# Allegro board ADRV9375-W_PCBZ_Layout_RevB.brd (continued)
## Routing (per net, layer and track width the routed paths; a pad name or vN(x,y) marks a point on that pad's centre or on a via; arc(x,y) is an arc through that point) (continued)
VDD_IF: length 250.6
  TOP w0.203: U403.8 117.21,60.84 v1(117.49,60.57)
  TOP w0.254: U101.M12 v2(38.04,50.78)
  TOP w0.305: R513.1 97.56,57.13 v1(97.05,57.64) ; R512.1 100.09,52.69 v1(100.09,52.12) 100.09,51.22 98.32,49.45 93.34,49.45 R510.1 ; U405.1 118.84,60.76 118.64,60.57 v1(117.49,60.57) ; R511.1 v1(94.81,57.64) ; U405.8 v1(122.74,66.3) ; 51.03,16.31 51.35,15.99 U702.2 ; 51.01,17.05 51.41,16.64 U702.1 ; R606.1 55.25,26.09 v1(56.78,24.56) ; v1(123.51,32.78) 122.53,33.76 U404.1 120.98,33.76 120.51,34.24 120.51,34.57 120.01,35.06 U404.4 ; v2(137.83,52.96) 137.92,53.04 R809.1 R808.1 ; R739.2 50.3,16.65
  TOP w0.394: P504.1 v1(43.47,72.38) ; R503.1 132.75,25.02 v2(132.75,25.02)
  TOP w0.508: P707.1 48.08,15.29 ; P707.1 47,14.21 ; P707.1 47,16.37 ; P707.1 45.92,15.29
  TOP w0.762: v1(131.48,22.48) 131.45,22.45 R738.2
  L3_PWR w0.508: v1(94.81,57.64) 95.64,58.46 96.52,58.46 97.05,57.93 v1(97.05,57.64) 100.09,54.61 v1(100.09,52.12)
  L3_PWR w0.635: v1(77.1,31.42) v1(77.86,31.42) 77.87,31.41 v1(78.75,31.41) 80.03,30.12 85.37,30.12 85.83,29.67 93.51,29.67 95.23,27.96 118.91,27.96 119.45,28.49 122.21,28.49 123.51,29.8 ; v1(131.48,22.48) 132.75,23.75 v2(132.75,25.02) 131.5,26.27 127.04,26.27 123.51,29.8 ; 123.51,29.8 v1(123.51,32.78)
  L12_PWR w0.203: 56.78,22.65 v1(56.78,24.56)
  L12_PWR w0.508: 125.36,52.88 125.36,59.86 122.74,62.49 v1(122.74,66.3) ; P707.1 48.08,15.29 ; P707.1 45.92,15.29 ; P707.1 47,14.21 ; P707.1 47,16.37 ; v1(117.49,60.57) 116.28,60.57 115.2,59.48 115.2,53.13
  L12_PWR w0.762: 78.5,57.7 78.5,58.59 76.97,60.12 72.65,60.12 71.38,61.39 71.38,67.1 69.99,68.5 69.99,72.82 68.34,74.47 45.56,74.47 v1(43.47,72.38) ; v2(38.04,50.78) 41.47,50.78 43.63,52.94 45.53,52.94 48.27,55.67 76.08,55.67
  BOTTOM w0.305: v2(38.04,50.78) 38.05,50.79 C642.1 ; C642.1 R502.1 ; C642.1 38.05,52.33 C643.1
  BOTTOM w0.394: v1(122.74,66.3) 122.81,66.23 C417.2 ; C415.2 122.7,33.33 123.26,32.78 v1(123.51,32.78) 123.51,34.14 125.61,36.24 v1(125.61,36.88) ; P801.J39 v2(132.75,25.02) ; P801.K40 v1(131.48,22.48)
  BOTTOM w0.508: C734.2 49.64,16.06 C735.2
  BOTTOM w0.762: C734.2 48.87,15.29 P707.1
VDD_IF_LDO: length 2.9
  TOP w0.254: 58.1,16.32 58.1,15.16 57.63,14.69 U702.5
  TOP w0.305: U702.7 56.66,16.06
  vias: v1(57.41,17.5) v1(58.47,18.72) v1(58.43,17.45) v1(58.94,18.08) v1(59.45,18.72) v1(59.45,17.51)
VDDA_CALPLL: length 17.1
  TOP w0.254: v2(33.24,43.58) U101.G4
  L7_SIG w0.203: v2(33.24,43.58) 33.5,43.58 33.88,43.19 34.16,43.19 34.43,42.93 34.43,41.58
  L7_SIG w0.394: 34.43,41.58 34.43,36.88 33.03,35.48 32.49,35.48 31.89,34.88 v1(31.89,33.19)
  BOTTOM w0.305: v2(33.24,43.58) 33.24,43.69 33.62,44.07 C615.1
  BOTTOM w0.508: v1(31.89,33.19) 31.89,31.99 C614.1 32.11,31.77 32.11,30.34 E602.2
VDDA_CLK: length 4.7
  TOP w0.254: v2(38.84,41.18) U101.N1
  BOTTOM w0.305: C616.1 41.03,40.76 E603.2 ; v2(38.84,41.18) 38.89,41.12 C617.1 40.47,41.12 40.86,40.74
  BOTTOM w0.394: C616.1 40.86,40.74
VDDA_CLKSYNTH: length 23.2
  TOP w0.254: v2(33.24,45.18) U101.G6
  L3_PWR w0.127: v1(47.25,40.43) 47,40.69 41.54,40.69 39.99,39.14 36.97,39.14 36.42,39.68 36.06,39.68 34.42,41.33 34.42,44.53 34.2,44.76 33.66,44.76 v2(33.24,45.18)
  BOTTOM w0.305: v1(47.25,40.43) 47.17,40.35 E604.2 46.08,40.36 C618.1 ; C619.1 33.23,45.18 v2(33.24,45.18)
VDDA_DES: length 38.8
  TOP w0.254: v2(39.64,47.58) U101.P9 v2(39.64,48.38) ; U101.N9 v2(38.84,48.38)
  BOTTOM w0.305: C653.1 38.76,49.91 38.76,49.6 38.42,49.26 C654.1 38.42,48.8 v2(38.84,48.38) v2(39.64,48.38) 39.64,48.05 v2(39.64,47.58)
  BOTTOM w0.508: 39.64,48.05 39.71,48.13 48.95,48.13 52.71,44.37 55,44.37 59.73,39.64 59.73,38.32 61.55,36.5 61.73,36.5 62.6,35.63 C652.1 62.23,33.93 60.05,33.93 E613.2
VDDA_RXLO: length 17
  TOP w0.254: U101.C6 v2(30.04,45.18)
  L12_PWR w0.508: v4(25.66,43.99) 21.6,39.92 v1(20.96,39.92)
  BOTTOM w0.203: C621.1 28.46,45.18
  BOTTOM w0.305: C620.1 26.45,45.5 27.2,45.5 27.52,45.18 v2(30.04,45.18)
  BOTTOM w0.394: C620.1 26.17,45.51 25.79,45.13 25.79,44.12 v4(25.66,43.99)
  BOTTOM w0.508: E605.2 17.76,40.92 20.29,40.92 20.71,40.5 20.71,40.18 v1(20.96,39.92)
VDDA_RXSYNTH: length 25.6
  TOP w0.254: U101.G9 v2(34.04,47.58)
  L5_SIG w0.114: 34.39,45.3 33.57,46.12 33.57,47.11 v2(34.04,47.58)
  L5_SIG w0.127: 34.39,45.3 34.39,41.1
  L5_SIG w0.203: 34.39,41.1 35.77,39.72 36.44,39.72 37.02,39.14 39.99,39.14 41.83,40.98 43.4,40.98
  L5_SIG w0.305: v1(45.6,38.15) 45.6,38.63 45.81,38.83 45.81,39.75 44.57,40.98 43.4,40.98
  BOTTOM w0.305: C623.1 34.07,47.54 v2(34.04,47.58) ; E606.2 C622.1 45.87,37.37 45.6,37.64 v1(45.6,38.15)
VDDA_RXTX: length 33.8
  TOP w0.203: v2(33.24,42.78) U101.F2
  L10_SIG w0.203: 34.05,41.45 34.42,41.82 34.42,42.13 34.16,42.39 33.88,42.39 33.56,42.72 33.29,42.72 v2(33.24,42.78) 33.24,42.49 33.66,42.07 33.66,41.82 34.03,41.45 34.05,41.45
  L10_SIG w0.394: v1(42.43,26.21) v1(41.67,26.21) 40.9,26.97 40.05,26.97 37.49,29.53 37.18,29.53 35.36,31.34 35.36,34.29 34.68,34.97 34.68,40.79 34.03,41.45
  BOTTOM w0.305: v2(33.24,42.78) 33.47,42.78 33.75,43.06 C610.1 35.26,43.06 C609.1
  BOTTOM w0.394: v1(41.67,26.21) v1(42.43,26.21) 43.95,26.21 44.71,26.97 C608.1 48.27,26.97
VDDA_RXVCO: length 21.4
  TOP w0.254: U101.C7 v2(30.04,45.98)
  L12_PWR w0.394: v4(27.19,46.53) 26.42,46.53 24.9,45 24.66,45 v1(24.16,44.5)
  BOTTOM w0.305: C624.1 27.96,46.78 28.33,46.78 28.62,46.49 C625.1 29,46.49 29.52,45.98 v2(30.04,45.98)
  BOTTOM w0.394: v4(27.19,46.53) 27.58,46.92 C624.1 ; 11.44,42.97 11.57,43.1 23.12,43.1 24.01,43.99 24.01,44.35 v1(24.16,44.5)
VDDA_SER: length 31.6
  TOP w0.254: U101.N8 v2(38.84,46.78) U101.P8 v2(39.64,46.78)
  BOTTOM w0.305: C613.1 39.96,46.78 v2(39.64,46.78) v2(38.84,46.78)
  BOTTOM w0.394: C613.1 40.2,45.56 C612.1
  BOTTOM w0.508: C612.1 40.47,45.69 40.48,45.69 46.16,45.69 46.24,45.77 47.63,45.77 48.61,44.8 48.61,44.54 51.36,41.79 53.9,41.79 56.88,38.8 C611.1 56.52,33.93 54.33,33.93 E601.2
VDDA_SNRXSYNTH: length 23.7
  TOP w0.254: U101.G7 v2(34.04,46.78)
  L12_PWR w0.127: 30.48,47.99 31,47.99 31.11,48.1 33.23,48.1 33.61,47.73 33.61,47.21 v2(34.04,46.78)
  L12_PWR w0.394: v1(21.92,49.32) 22.68,50.08 25.08,50.08 25.83,49.34 26.33,49.34 27.11,48.56 29.35,48.56 29.91,47.99 30.48,47.99
  BOTTOM w0.305: v2(34.04,46.78) 34.11,46.71 C627.1
  BOTTOM w0.394: E608.2 16.45,51.61 18.14,51.61 C626.1 20.11,52.09 22.11,50.08 22.11,49.51 v1(21.92,49.32)
VDDA_SNRXVCO: length 18.6
  TOP w0.254: v2(30.04,43.58) U101.C4
  L12_PWR w0.203: 27.17,42.64 28.52,43.99 29.63,43.99 v2(30.04,43.58)
  L12_PWR w0.508: v1(26.93,38.65) 27.31,39.04 27.31,41.19 27.19,41.31 27.19,41.32 27.17,41.34 27.17,42.64
  BOTTOM w0.203: C629.1 30.17,44.18 30.04,44.05 v2(30.04,43.58)
  BOTTOM w0.508: E609.2 24.23,31.35 C628.1 26.23,34.97 26.43,35.5 v1(26.93,38.65)
VDDA_TXLO: length 29.8
  TOP w0.254: v6(33.24,50.78) U101.F12
  L10_SIG w0.394: v5(34.03,50.71) 33.97,50.78 v6(33.24,50.78)
  L12_PWR w0.203: v5(34.03,50.71) 33.89,50.57 33.05,50.57 31.66,51.96 31.47,51.96
  L12_PWR w0.394: v1(15,63.42) 15.09,63.32 17.49,63.32 18.4,62.42 18.91,62.42 22.87,58.47 24.77,58.47 29.09,54.15 29.09,53.51 30.31,52.29 31.15,52.29 31.47,51.96
  BOTTOM w0.305: C635.1 34.07,50.75 v5(34.03,50.71)
  BOTTOM w0.394: E612.2 13.34,62.78 C634.1 v1(15,63.42)
VDDA_TXSYNTH: length 29.6
  TOP w0.254: v6(33.24,47.58) U101.G8
  L10_SIG w0.127: v6(33.24,47.58) 32.85,47.97 29.81,47.97 29.6,48.18 29.6,48.56 29.44,48.72 28.78,48.72 28.74,48.76
  L10_SIG w0.254: 28.74,48.76 27.97,48.76 27.57,49.16 27.57,50.2 27.82,50.46 27.82,52.37 28.08,52.62 v1(28.08,52.98) 24.65,56.4 20.42,56.4 19.33,55.31 15.3,55.31 v1(15.2,55.21)
  BOTTOM w0.305: C633.1 28.25,53.15 v1(28.08,52.98)
  BOTTOM w0.394: v1(15.2,55.21) 13.94,55.21 C632.1 13.73,55.16 E611.2
VDDA_TXVCO: length 32
  TOP w0.254: v6(33.24,49.18) U101.F11
  L5_SIG w0.203: 27.06,49.71 27.98,48.79 30.18,48.79 30.46,48.52 30.46,48.22 30.68,47.99 33.66,47.99 v5(34.04,48.38)
  L5_SIG w0.305: v6(33.24,49.18) 34.01,49.18 v5(34.04,49.21)
  L5_SIG w0.394: v1(15,59.8) 16.11,58.69 19.72,58.69 23.22,55.2 23.22,52.91 26.42,49.71 27.06,49.71
  BOTTOM w0.305: 34.04,48.81 v5(34.04,49.21) ; 34.04,48.81 34.04,48.38 v5(34.04,48.38) ; 34.04,48.81 C631.1
  BOTTOM w0.394: 12.57,59.79 12.58,59.8 C630.1 ; 12.57,59.79 E610.2 ; 12.57,59.79 13.94,59.79 C630.1 ; v1(15,59.8) C630.1
1P3_BUCK_OUT: length 25.4
  L8_SIG w0.394: v1(85.18,33.72) 84.4,32.94 77.23,32.94 75.41,31.12 75.41,20.1 v1(76.11,19.39) v1(76.87,19.39) v1(77.64,19.39)
  BOTTOM w0.394: v1(85.18,33.72) 85.59,33.31 R705.1
3P3V_CLK: length 43.2
  TOP w0.203: U404.6 119.82,33.58 v1(119.82,32.83)
  TOP w0.305: U405.14 v1(118.84,66.3)
  TOP w0.394: C436.2 v1(90.54,79.63) ; C437.2 v1(89.04,79.63) ; C431.2 v1(95.34,72.33) ; C422.2 v1(83.24,76.33) ; C433.2 v1(95.34,75.33) ; C421.2 v1(83.24,77.83) ; C438.2 v1(87.54,79.63) ; C429.2 v1(95.34,69.33) ; C434.2 v1(93.54,79.63) ; C439.2 v1(86.04,79.63) ; v1(85.94,67.54) 85.94,67.54 86.04,67.63 C426.2 ; C435.2 v1(92.04,79.63) ; C424.2 v1(83.28,73.33) ; C425.2 83.31,69.86 v1(83.2,69.75) ; C414.2 74.91,79.05 v1(74.93,79.04) ; v1(83.22,74.83) C423.2 ; C432.2 v1(95.34,73.83) ; C428.2 v1(93.54,67.53) ; C430.2 v1(95.34,70.83) ; C427.2 v1(89.04,67.53)
  BOTTOM w0.203: U401.16 86.04,68.45 ; U401.51 92.04,78.53 ; U401.1 v1(93.54,67.53) ; 94.41,70.83 94.41,70.83 U401.69 ; 89.04,68.45 89.04,68.45 U401.10 ; U401.45 89.04,78.53 ; U401.36 84.34,77.83 ; U401.63 94.24,73.83
  BOTTOM w0.254: v1(95.34,69.33) U401.72 ; U401.33 v1(83.24,76.33) ; v1(83.2,69.75) 83.66,69.75 83.72,69.81 83.8,69.81 83.82,69.83 U401.20 ; 84.34,77.83 v1(83.24,77.83) ; 89.04,78.53 v1(89.04,79.63) ; U401.39 v1(86.04,79.63) ; U401.42 87.54,79.63 v1(87.54,79.63) ; U401.27 v1(83.28,73.33) ; U401.30 v1(83.22,74.83) ; U401.54 v1(93.54,79.63) ; 86.04,68.45 86.04,67.63 85.94,67.54 v1(85.94,67.54) ; 92.04,78.53 v1(92.04,79.63) ; U401.66 v1(95.34,72.33) ; U401.60 v1(95.34,75.33) ; 94.24,73.83 v1(95.34,73.83) ; U401.48 v1(90.54,79.63) ; 89.04,68.45 v1(89.04,67.53) ; 94.41,70.83 v1(95.34,70.83)
  BOTTOM w0.305: U402.5 v1(74.93,79.04)
  BOTTOM w0.394: C420.1 93.55,79.63 v1(93.54,79.63) ; C416.2 v1(119.82,32.83) ; R416.1 82.98,69.53 v1(83.2,69.75) ; v1(118.84,66.3) 118.87,66.26 C418.2
  vias: v1(109.99,31.73) v1(109.99,30.97) v1(110.88,31.73) v1(110.88,30.97) v1(111.77,31.73) v1(111.77,30.97)
3P3V_VCO: length 65
  BOTTOM w0.305: 127.01,74.97 127.01,74.96 C738.2
  BOTTOM w0.394: Y401.6 Y403.4 Y402.6 C405.2 v1(109.41,76.5)
  BOTTOM w0.508: R408.2 124.35,72.91 124.82,73.39 125.56,74.13 v1(125.56,74.97) v1(126.23,74.97) 127.53,74.97 130.06,72.44 130.06,54.83 126.97,51.74 126.5,51.74 120.53,45.77 118.75,45.77 116.21,43.23 114.18,43.23 111.13,40.18 109.86,40.18 107.97,38.29 103.91,38.29 E706.2
3P3VAUX: length 101.7
  TOP w0.305: U601.17 U601.16 ; U601.10 v1(45.49,22.29) ; U801.8 C803.2 125.17,31.99 125.17,31.99 C804.1 127.52,31.96 v1(127.68,31.96) ; R818.2 113.21,33.43 v1(112.97,33.67) ; R820.2 v1(113.8,30.53) ; R822.2 v1(113.8,28.75)
  TOP w0.635: U601.16 50.55,22.29 51.2,21.64 v7(51.2,20.37)
  L10_SIG w0.394: v7(51.2,20.37) 50.18,21.38 46.4,21.38 v1(45.49,22.29)
  L10_SIG w0.762: v7(51.2,20.37) 52.84,20.37 57.03,16.18 59.19,16.18 61.6,13.76 106.05,13.76 113.8,21.51 v1(113.8,28.75) v1(113.8,30.53) 113.8,32.83 v1(112.97,33.67)
  BOTTOM w0.394: C648.1 51.19,20.38 v7(51.2,20.37) 50.91,20.37 50.22,21.07 C649.1 ; P801.D32 v2(139.1,33.91)
ADP5054_EN: length 108.4
  TOP w0.305: v1(79.68,31.76) 79.66,31.77 R702.1
  L8_SIG w0.394: v2(140.3,73.57) 142.46,73.57 143.57,72.45 143.57,38.84 143.52,38.78 143.52,38.74 141.89,37.12 141.39,37.12 137.17,32.89 137.17,32.39 135.52,30.74 127.56,30.74 126.25,32.05 122.82,32.05 122.42,32.45 121.66,32.45 121.39,32.18 120.1,32.18 120.09,32.17 119.55,32.17 119.54,32.18 116.34,32.18 115.71,32.81 98.31,32.81 97.31,31.81 79.73,31.81 v1(79.68,31.76)
  BOTTOM w0.394: v2(140.3,73.57) 139.74,73.01 P801.D1
ADP5054_VREG: length 20.4
  TOP w0.394: v1(89.62,30.8) 91.4,29.02 91.4,21.83 v1(91.07,21.5) 91.04,21.53 91.04,21.68 90.64,22.08 88.95,22.08 v1(88.25,21.38) 87.86,20.99 87.86,20.73 R703.2
  BOTTOM w0.203: C702.2 89.7,30.87 v1(89.62,30.8) 89.03,30.2 ; 89.03,30.2 88.75,29.92 U701.44 ; 89.03,30.2 89.25,29.98 U701.45
  BOTTOM w0.254: v1(91.07,21.5) 90.75,21.82 U701.13 ; U701.18 v1(88.25,21.38)
AUXADC_0: length 66
  TOP w0.254: U101.E13 v6(31.64,51.58)
  L5_SIG w0.114: P501.3 81.29,66.02 79.13,68.18 72.46,68.18 70.3,66.02 70.3,61.96 68.38,60.04 47.71,60.04 47.22,60.53 46.14,60.53 45.65,60.04 44.68,60.04 44.38,60.34 44.38,60.38 44.26,60.5 39.82,60.5 37.86,58.53 36.65,58.53 34.68,56.56 34.68,53.13 32.79,51.24 31.97,51.24 v6(31.64,51.58)
  BOTTOM w0.203: C506.1 P501.3
AUXADC_1: length 90
  TOP w0.254: U101.C11 v6(30.04,49.98)
  L5_SIG w0.114: P501.4 82.46,63.58 82.46,67.33 80.43,69.35 68.17,69.35 67.84,69.02 66.29,69.02 65.82,69.5 63.15,69.5 61.86,70.79 55.82,70.79 54.9,69.87 47.84,69.87 47.8,69.9 47,69.9 45.86,68.75 40.78,68.75 37.47,72.06 35.7,72.06 35.63,72.13 31.71,72.13 31.27,71.69 30,71.69 28.77,70.47 28.77,67.55 28.08,66.85 27.44,66.85 26.99,66.4 26.99,61.56 26.53,61.09 26.51,61.09 25.66,60.24 25.66,56.01 28.77,52.9 28.77,52.18 29.04,51.91 29.38,51.91 29.6,51.69 29.6,50.41 v6(30.04,49.98)
  BOTTOM w0.203: C505.1 P501.4
AUXADC_2: length 64.2
  TOP w0.254: U101.C12 v6(30.04,50.78)
  L5_SIG w0.114: P501.5 78.75,66.02 77.29,67.48 72.84,67.48 70.88,65.52 70.88,61.99 70.88,61.99 70.88,61.56 70.88,61.56 70.88,61.04 69.19,59.36 46.93,59.36 46.68,59.61 39.76,59.61 38.01,57.86 36.94,57.86 35.19,56.11 35.19,53.13 33.97,51.91 33.9,51.91 33.7,51.72 32.39,50.4 30.41,50.4 v6(30.04,50.78)
  BOTTOM w0.203: 78.75,66.42 P501.5
AUXADC_3: length 64.8
  TOP w0.254: U101.D11 v6(30.84,49.98)
  L5_SIG w0.114: v6(30.84,49.98) 31.17,49.64 32.58,49.64 32.9,49.96 32.9,50.12 33.1,50.31 33.38,50.31 33.7,50.63 33.7,50.85 33.9,51.05 34.12,51.05 34.43,51.35 34.43,51.86 35.63,53.07 35.63,55.12 36.28,55.77 36.39,55.77 37.44,56.82 39.25,56.82 40.59,58.15 42.62,58.15 43.5,59.04 45.1,59.04 45.42,58.72 69.48,58.72 71.38,60.63 71.38,65.13 73.22,66.98 75.89,66.98 77.42,65.45 77.42,63.74 P501.6
  BOTTOM w0.203: 78.75,60.93 P501.6
BAL_TX_OUT1: length 1
  TOP w0.203: 35.44,63.14 35.44,63.48 ; 35.44,64.07 C305.1
  TOP w0.394: 35.44,63.48 35.44,64.07
BAL_TX_OUT2: length 1
  TOP w0.203: 34.24,30.41 34.23,30.07 ; C306.1 34.23,29.48
  TOP w0.394: 34.23,29.48 34.23,30.07
CLK+: length 7.5
  BOTTOM w0.203: U401.2 93.04,67.83 92.97,67.76 92.97,65.32 92.06,64.42 92.06,63.69 92.28,63.47 92.72,63.47 ; C402.2 93.54,63.47 92.72,63.47 ; R406.1 92.72,63.47
CLK-: length 8.1
  BOTTOM w0.203: U401.3 92.54,67.83 92.61,67.76 92.61,65.47 91.7,64.56 91.7,63.55 92.13,63.12 92.72,63.12 ; C403.2 93.54,63.12 92.72,63.12 ; 92.72,63.12 R406.2
CLK_RESETB: length 109.6
  TOP w0.203: v1(120.18,35.62) 119.33,35.62 119.1,35.38 119.1,34.74 119.43,34.41 U404.5
  L7_SIG w0.114: v1(120.18,35.62) 120.18,35.45 120.91,34.72 125.36,34.72 127.64,37 135.24,37 137.37,39.14 137.37,39.18 137.64,39.45 137.69,39.45 138.87,40.64 138.87,41.25 142.25,44.62 142.25,59.61 141.94,59.92 137.82,59.92 137.68,59.77 134.72,59.77 132.09,62.4 127.39,62.4 125.23,64.56 117.61,64.56 114.94,67.23 94.75,67.23 92.92,69.06 v1(83.45,69.06)
  BOTTOM w0.203: v1(83.45,69.06) 83.72,69.33 U401.19
  BOTTOM w0.394: R416.2 82.93,68.54 v1(83.45,69.06)
CLK_SYSREF_REQUEST: length 32.4
  TOP w0.203: U405.13 v1(119.49,69.23)
  L7_SIG w0.114: v1(119.49,69.23) 117.04,71.67 102.75,71.67 99.96,74.47 98.31,74.47 96.53,76.24 v1(96.53,77.8)
  BOTTOM w0.254: U401.57 94.92,76.83 95.57,76.83 v1(96.53,77.8) ; R417.2 97.17,77.8
  BOTTOM w0.394: 97.17,77.8 v1(96.53,77.8)
COMP_OUT: length 4.9
  BOTTOM w0.203: Y401.5 Y402.5 111.38,73.96 110.59,73.18 R411.1
DEV_CLK_IN+: length 66.7
  BOTTOM w0.203: 32.21,48.56 32.21,49.34 arc(32.44,50.7) 33.1,51.9 arc(35.41,53.73) 38.29,54.35 42.12,54.35 arc(44.94,55.52) 46.11,58.34 46.11,63.14 arc(47.52,66.56) 50.94,67.97 50.94,67.97 arc(58.87,68.59) 66.64,70.3 arc(73.86,71.88) 81.24,72.41 81.75,72.41 ; 32.21,48.56 R501.2 ; 32.21,48.56 32.21,48.29 arc(32.24,48.12) C502.1 ; 81.75,72.41 83.63,72.41 83.72,72.33 U401.25 ; 81.75,72.41 R425.1
DEV_CLK_IN-: length 67.3
  BOTTOM w0.203: U401.26 83.68,72.83 83.62,72.77 81.75,72.77 ; 81.75,72.77 R425.2 ; 81.75,72.77 81.24,72.77 arc(73.81,72.23) 66.54,70.64 arc(58.82,68.94) 50.94,68.32 arc(47.27,66.81) 45.75,63.14 45.75,58.34 arc(44.69,55.77) 42.12,54.7 38.29,54.7 arc(35.26,54.05) 32.83,52.13 arc(32.1,50.82) 31.85,49.34 31.85,48.56 ; 31.85,48.56 R501.1 ; 31.85,48.56 31.85,48.29 arc(31.81,48.12) C501.1
DIR_CLK+: length 4.6
  BOTTOM w0.203: 96.02,63.47 95.2,63.47 C402.1 ; 96.02,63.47 R405.1 ; 96.02,63.47 96.85,63.47 R403.2 97.49,64.12 97.99,64.12 98.43,64.56 T401.1
DIR_CLK-: length 4.6
  BOTTOM w0.203: C403.1 95.2,63.12 96.02,63.12 ; 96.02,63.12 96.83,63.12 R404.1 97.46,62.49 98.01,62.49 98.48,62.02 T401.3 ; 96.02,63.12 R405.2
EPROM_A0: length 115.9
  TOP w0.203: U601.11 47.52,20.89 v1(46.87,20.24)
  TOP w0.305: R818.1 R819.2 115.77,32.79 116.61,31.95 U801.1 118.85,31.95 v1(119.89,30.91)
  L8_SIG w0.114: v1(46.87,20.24) 48.39,21.76 52.34,21.76 57.67,16.43 80.78,16.43 81.86,17.51 94.18,17.51 102.5,25.83 114.31,25.83 119.39,30.91 v1(119.89,30.91)
  L10_SIG w0.114: v1(119.89,30.91) 124.08,26.72 136.53,26.72 137.37,27.55 137.37,27.75 139.72,30.1 v2(141.64,30.1)
  BOTTOM w0.394: P801.C34 v2(141.64,30.1)
EPROM_A1: length 115.9
  TOP w0.203: U601.13 48.52,20.62 v1(48.14,20.24)
  TOP w0.305: R820.1 R821.2 116.11,31.65 116.46,31.3 U801.2 118.64,31.3 v1(118.85,31.09)
  L8_SIG w0.114: v1(48.14,20.24) 49.03,21.13 52.21,21.13 57.61,15.73 97.23,15.73 105.8,24.3 114.31,24.3 120.53,30.53 120.53,31.03 120.02,31.54 119.26,31.54 118.85,31.13 v1(118.85,31.09)
  L10_SIG w0.114: v1(118.85,31.09) 123.98,25.95 137.5,25.95 v2(140.37,28.83)
  BOTTOM w0.394: P801.D35 v2(140.37,28.83)
FMC_CLK_RESETB: length 24
  TOP w0.305: v2(140.37,41.53) 138.57,39.73 138.57,37.52 136.91,35.86 130.82,35.86 130.37,35.41 123.77,35.41 122.77,34.41 U404.2
  BOTTOM w0.394: v2(140.37,41.53) P801.D26
FMC_SYSREF_REQUEST: length 48.9
  TOP w0.203: U405.2 v1(119.49,63.29)
  L8_SIG w0.114: v1(119.49,63.29) 121.74,61.03 125.84,61.03 126.86,62.05 129.4,62.05 132.77,58.67 140.65,58.67 142.25,57.07 142.25,48.64 141.92,48.31 141.48,48.31 140.97,47.8 140.22,47.8 139.35,46.94 139.35,40.01 v2(140.37,38.99)
  BOTTOM w0.394: v2(140.37,38.99) P801.D27
FMCA_SCL: length 107.4
  TOP w0.203: v1(50.05,20.24) 49.52,20.76 U601.15
  TOP w0.305: U801.6 122.19,30.65 v1(121.8,31.03)
  L8_SIG w0.114: v1(50.05,20.24) 51.57,18.72 53.73,18.72 57.41,15.03 108.21,15.03 114.25,21.07 114.25,23.22 120.91,29.89 120.91,30.15 v1(121.8,31.03)
  L10_SIG w0.114: v2(141.64,35.18) 141.06,34.59 133.87,34.59 130.69,31.41 122.68,31.41 122.31,31.03 v1(121.8,31.03)
  BOTTOM w0.394: v2(141.64,35.18) P801.C30
FMCA_SDA: length 110
  TOP w0.203: U601.14 v1(49.02,20.24)
  TOP w0.305: v1(121.82,30) U801.5
  L8_SIG w0.114: v1(121.82,30) 121.82,29.91 114.75,22.84 114.75,20.43 108.59,14.27 53.6,14.27 49.02,18.85 v1(49.02,20.24)
  L10_SIG w0.114: v1(121.82,30) 123.98,30 125.1,28.88 126.88,28.88 127.52,29.51 137.3,29.51 141.64,33.86 v2(141.64,33.91)
  BOTTOM w0.394: v2(141.64,33.91) P801.C31
FMCA_VADJ: length 13.2
  TOP w0.762: 131.44,19.44 129.45,19.44 TP812.1 ; 131.44,19.44 131.45,19.43 C732.1 ; 131.44,19.44 R738.1
  L12_PWR w0.508: TP812.1 128.3,21.61 ; TP812.1 129.31,20.59 ; TP812.1 127.28,20.59 ; TP812.1 128.3,19.57
  BOTTOM w0.394: P801.G39 v2(136.56,23.75) ; P801.E39 v2(139.1,23.75) ; P801.F40 v2(137.83,22.48) ; P801.H40 v2(134.02,23.75)
FMCA_VCC_3P3V: length 7.7
  L12_PWR w0.508: TP816.1 129.39,23.89 ; TP816.1 128.37,22.87 ; TP816.1 127.36,23.89 ; TP816.1 128.37,24.91
  BOTTOM w0.394: P801.C39 v2(141.64,23.75) ; P801.D38 v2(140.37,25.02) ; P801.D40 v2(140.37,22.48) ; P801.D36 v2(140.37,27.56)
FMCA_VCC_12P0V: length 5.9
  TOP w0.508: TP815.1 121.29,27.61 ; TP815.1 121.29,25.57 ; TP815.1 120.28,26.59 ; TP815.1 122.31,26.59
  BOTTOM w0.394: P801.C35 v2(141.64,28.83) ; P801.C37 v2(141.64,26.29)
FPGA_AUX_CLK+: length 49.2
  TOP w0.203: C805.1 140.22,70.09 139.16,71.14 138.97,71.14 137.82,72.28 134.97,72.28 134.18,73.07 131.58,73.07 130.43,74.23 126.7,74.23 126.5,74.02 122.88,74.02 121.93,74.98 102.3,74.98 v1(102.28,75)
  BOTTOM w0.203: v1(102.28,75) 102.05,74.76 99.07,74.76 ; 99.07,74.76 R429.1 ; 99.07,74.76 95.1,74.76 95.04,74.83 U401.61
FPGA_AUX_CLK-: length 49.2
  TOP w0.203: v1(102.28,74.18) 102.72,74.62 121.78,74.62 122.73,73.67 126.65,73.67 126.85,73.87 130.28,73.87 131.43,72.72 134.04,72.72 134.82,71.93 137.68,71.93 138.82,70.79 139.02,70.79 139.86,69.94 139.86,69.76 139.71,69.6 139.71,69.45 139.58,69.33 C806.1
  BOTTOM w0.203: R429.2 99.07,74.4 ; 99.07,74.4 95.11,74.4 95.04,74.33 U401.62 ; 99.07,74.4 99.07,74.41 99.68,74.41 102.06,74.41 v1(102.28,74.18)
FPGA_REF_CLK+: length 82
  TOP w0.203: v1(97.65,73.49) 98.35,73.49 103.51,78.66 132.22,78.66 133.8,77.07 141.23,77.07 145.93,72.37 145.93,62.59 146.14,62.39 146.14,61.27 145.25,60.39 145.25,51.27 144.55,50.56 143.47,50.56 143.27,50.36 C801.2
  BOTTOM w0.203: v1(97.65,73.49) 97.41,73.26 96.63,73.26 ; R422.1 96.63,73.26 ; 96.63,73.26 95.11,73.26 95.04,73.33 U401.64
FPGA_REF_CLK-: length 82
  TOP w0.203: C802.2 142.57,49.01 142.76,49.2 142.76,49.28 142.91,49.44 142.91,50.51 143.32,50.92 144.4,50.92 144.89,51.41 144.89,60.54 145.78,61.42 145.78,62.24 145.58,62.45 145.58,72.23 141.09,76.72 133.66,76.72 132.07,78.3 103.66,78.3 98.49,73.14 98.11,73.14 v1(97.65,72.68)
  BOTTOM w0.203: R422.2 96.63,72.9 ; 96.63,72.9 95.11,72.9 95.04,72.83 U401.65 ; 96.63,72.9 97.43,72.9 v1(97.65,72.68)
FPGA_SYSREF+: length 98.5
  L7_SIG w0.091: v2(136.56,27.56) 136.45,27.56 136.06,27.96 136.06,28.59 139.39,31.92 142,31.92 143.65,33.57 143.65,40.18 144.46,41 144.8,41 146.06,42.25 146.06,44.62 145.3,45.39 145.3,61.01 143.77,62.53 142.23,62.53 137.07,67.69 133.66,67.69 131.07,70.28 122.8,70.28 117.46,75.61 108.53,75.61 107.65,76.49 v1(98.79,76.49)
  BOTTOM w0.203: 96.72,76.26 95.16,76.26 95.09,76.33 94.47,76.33 U401.58 ; 96.72,76.26 R423.2 ; 96.72,76.26 97.33,76.26 98.56,76.26 v1(98.79,76.49)
  BOTTOM w0.394: P801.G36 v2(136.56,27.56)
FPGA_SYSREF-: length 98.5
  L7_SIG w0.091: v1(98.79,75.68) 99.35,76.24 107.54,76.24 108.43,75.36 117.36,75.36 122.69,70.02 130.97,70.02 133.55,67.44 136.96,67.44 142.12,62.28 143.67,62.28 145.04,60.9 145.04,45.28 145.81,44.52 145.81,42.36 144.7,41.25 144.36,41.25 143.39,40.28 143.39,33.68 141.89,32.18 139.28,32.18 135.8,28.7 135.8,27.76 135.6,27.56 v2(135.29,27.56)
  BOTTOM w0.203: 96.72,75.9 95.16,75.9 95.09,75.83 U401.59 ; 96.72,75.9 R423.1 ; 96.72,75.9 97.33,75.9 98.56,75.91 98.57,75.91 v1(98.79,75.68)
  BOTTOM w0.394: P801.G37 v2(135.29,27.56)
GP_INTERRUPT: length 113.4
  TOP w0.254: U101.J5 v6(35.64,45.18)
  TOP w0.394: R803.1 134.25,59.91 134.18,59.98 129.71,59.98 TP803.1
  L7_SIG w0.114: TP803.1 127.72,58.1 122.37,52.75 103.64,52.75 99.83,56.56 89.69,56.56 87.64,54.51 87.64,53.91 86.48,52.75 85.73,52.75 84.89,51.9 84.89,49.87 83.18,48.16 82.8,48.16 78.22,43.58 78.19,43.58 77.88,43.28 77.88,43.25 77.19,42.55 55.15,42.55 54.93,42.78 52.53,42.78 51.98,43.33 46.77,43.33 45.26,44.84 40.14,44.84 40.14,44.84 38.7,44.84 38.37,45.16 38.37,45.32 38.18,45.51 37.9,45.51 37.7,45.32 37.7,45.16 37.38,44.84 35.97,44.84 v6(35.64,45.18)
GPIO_0: length 110.5
  TOP w0.254: U101.K8 v6(36.44,47.58)
  TOP w0.305: R513.2 R517.1 96.26,54.23 P502.2
  L7_SIG w0.114: v2(134.02,50.42) 133.82,50.21 130.01,50.21 129.76,50.46 129.34,50.46 129.07,50.2 126.95,50.2 126.81,50.34 100.15,50.34 P502.2
  L8_SIG w0.114: v6(36.44,47.58) 36.69,47.58 37.08,47.19 39.77,47.19 40.31,46.66 43.15,46.66 43.41,46.92 44.65,46.92 44.74,46.83 45.16,46.83 45.63,47.29 46.91,47.29 47.78,48.16 50.03,48.16 51.19,49.32 66.3,49.32 72.4,55.42 79.61,55.42 79.62,55.41 80.04,55.41 80.05,55.42 81.03,55.42 82.05,56.43 94.88,56.43 96.4,54.91 P502.2
  BOTTOM w0.394: v2(134.02,50.42) P801.H19
GPIO_1: length 125.5
  TOP w0.254: U101.J8 v6(35.64,47.58)
  TOP w0.305: 98.62,52.88 98.62,52.37 R516.1 ; 98.62,52.88 R512.2 ; 98.62,52.88 95.2,52.88 P502.3
  L7_SIG w0.114: P502.3 96.09,49.31 117.63,49.31 117.64,49.32 130.91,49.32 131.55,48.69 132.56,48.69 132.56,48.69 132.95,48.69 132.95,48.69 133.56,48.69 v2(134.02,49.15)
  L8_SIG w0.114: P502.3 93.86,50.34 91.77,48.24 91.77,44.69 90.56,43.48 90.56,42.97 85.86,38.27 59.32,38.27 58.56,37.51 54.49,37.51 54.11,37.13 45.22,37.13 43.45,38.9 42.05,38.9 40.14,40.81 37.6,40.81 36.78,41.64 36.3,41.64 36.1,41.84 36.1,42.06 34.43,43.74 34.43,46.84 34.75,47.16 35.23,47.16 v6(35.64,47.58)
  BOTTOM w0.394: v2(134.02,49.15) P801.H20
GPIO_2: length 123.6
  TOP w0.254: U101.J7 v6(34.84,45.98)
  TOP w0.305: R511.2 R515.1 93.52,54.43 P502.4
  L7_SIG w0.114: P502.4 94.97,55.2 98.28,55.2 102.54,50.94 123.76,50.94 124.05,51.23 129.81,51.23 130.21,51.64 130.66,51.64 131.2,51.1 135.88,51.1 v2(136.56,50.42)
  L8_SIG w0.114: v6(34.84,45.98) 34.68,45.82 34.68,43.99 36.33,42.34 36.71,42.34 37.41,41.64 39.95,41.64 41.41,40.18 46.49,40.18 47.77,38.9 53.6,38.9 54.54,39.84 84.89,39.84 88.04,43 88.04,43.5 90.99,46.46 90.99,49 92.47,50.47 92.47,52.69 P502.4
  BOTTOM w0.394: v2(136.56,50.42) P801.G18
GPIO_3: length 119.7
  TOP w0.254: U101.K7 v6(36.44,46.78)
  TOP w0.305: R510.2 91.51,49.32 R514.1
  TOP w0.394: P502.5 91.46,51.41 R514.1
  L7_SIG w0.114: P502.5 93.67,49.2 93.69,49.2 94,48.9 94,48.87 95.33,47.53 115.72,47.53 116.16,47.09 118.68,47.09 119.01,47.42 133.83,47.42 133.83,47.42 134.22,47.42 134.22,47.42 134.83,47.42 v2(136.56,49.15)
  L8_SIG w0.114: v6(36.44,46.78) 36.44,45.75 35.97,45.28 35.97,45.04 35.78,44.84 35.63,44.84 35.3,44.52 35.3,44.24 35.63,43.91 35.78,43.91 36.08,43.61 36.08,43.46 36.43,43.11 36.58,43.11 36.9,42.79 36.9,42.64 37.2,42.34 40.01,42.34 41.28,41.07 48.26,41.07 48.77,40.57 52.21,40.57 52.33,40.69 62.33,40.69 62.33,40.68 83.07,40.68 83.37,40.99 83.37,41.25 89.23,47.1 89.23,49.13 91.32,51.23 P502.5
  BOTTOM w0.394: v2(136.56,49.15) P801.G19
GPIO_3P3_0: length 59.1
  TOP w0.254: v6(29.35,40.63) 29.49,40.63 U101.C1
  L8_SIG w0.114: v6(29.35,40.63) 29.24,40.63 28.85,41.02 28.85,41.53 28.46,41.93 28.46,43.74 28.81,44.08 28.81,47.62 29.23,48.04 29.38,48.04 29.39,48.05 29.4,48.05 29.7,48.36 29.7,48.52 29.9,48.71 30.09,48.71 31.3,49.92 31.3,50.12 31.5,50.31 31.66,50.31 33.54,52.19 33.54,54.46 38.81,59.74 39.13,59.74 40.65,61.26 40.65,62.66 46.49,68.5 48.52,68.5 48.78,68.25 49.67,68.25 50.05,68.63 61.48,68.63 64.02,66.09 P503.5
  BOTTOM w0.203: P503.5 64.02,66.37
GPIO_3P3_1: length 52.3
  TOP w0.254: U101.C2 v6(30.04,41.98)
  L8_SIG w0.114: v6(30.04,41.98) 29.65,42.36 29.65,47.72 29.97,48.04 30.18,48.04 30.5,48.36 30.5,48.52 30.7,48.71 30.89,48.71 31.3,49.12 31.3,49.32 31.5,49.51 31.69,49.51 32.04,49.86 32.04,50.11 34.05,52.12 34.05,53.64 36.3,55.89 36.55,55.89 37.47,56.82 39.51,56.82 40.65,57.96 40.65,59.23 43.06,61.64 43.06,63.67 44.97,65.58 45.86,65.58 47.51,67.23 50.3,67.23 50.81,67.74 56.14,67.74 57.41,66.47 59.95,66.47 P503.7
  BOTTOM w0.203: P503.7 61.48,66.37
GPIO_3P3_2: length 43
  TOP w0.254: U101.F1 v6(32.44,41.18)
  L8_SIG w0.114: P503.9 57.67,63.67 57.67,62.1 49.84,54.28 45.35,54.28 43.44,52.37 40.47,52.37 40.12,52.72 37.44,52.72 36.84,52.12 36.84,50.6 36.56,50.31 36.3,50.31 36.1,50.12 36.1,49.85 35.76,49.51 35.5,49.51 35.3,49.32 35.3,49.05 35.04,48.79 34.78,48.79 34.37,48.39 34.37,48.24 34.18,48.04 33.95,48.04 33.57,47.66 33.57,47.44 33.38,47.24 33.23,47.24 32.9,46.92 32.9,46.91 32.85,46.86 32.85,44.31 32.45,43.91 32.3,43.91 32.1,43.72 32.1,41.51 v6(32.44,41.18)
GPIO_3P3_3: length 44.8
  TOP w0.254: U101.D1 31.2,41.54 v6(31.2,41.01)
  L8_SIG w0.114: P503.11 55.13,66.21 50.3,66.21 45.98,61.9 45.98,60.75 40.24,55.01 36.98,55.01 36.7,54.74 36.41,54.74 34.5,52.83 34.5,51.56 33.99,51.05 33.9,51.05 33.7,50.85 33.7,50.76 33.25,50.31 33.1,50.31 32.9,50.12 32.9,49.96 31.66,48.71 31.5,48.71 31.3,48.52 31.3,48.36 30.98,48.04 30.83,48.04 30.43,47.64 30.43,41.79 v6(31.2,41.01)
  BOTTOM w0.203: P503.11 C525.1
GPIO_3P3_4: length 40.6
  TOP w0.254: U101.E1 v6(31.64,41.18)
  L8_SIG w0.114: v6(31.64,41.18) 31.25,41.56 31.25,43.66 31.5,43.91 31.72,43.91 32.05,44.24 32.05,46.95 33.14,48.04 33.38,48.04 33.57,48.24 33.57,48.6 33.82,48.84 34.15,48.84 34.37,49.07 34.37,49.27 34.71,49.6 34.96,49.6 35.3,49.94 35.3,50.12 35.5,50.31 35.67,50.31 35.97,50.62 35.97,52.65 37.35,54.02 42.94,54.02 44.46,55.55 46.75,55.55 52.59,61.39 52.59,63.67 P503.13
  BOTTOM w0.203: P503.13 C526.1
GPIO_3P3_5: length 35
  TOP w0.254: U101.D5 v6(30.84,44.38)
  L8_SIG w0.114: v6(30.84,44.38) 31.23,44.77 31.23,47.02 32.25,48.04 32.58,48.04 32.77,48.24 32.77,48.56 33.05,48.84 33.38,48.84 33.57,49.04 33.57,49.36 34.65,50.44 34.98,50.44 35.3,50.76 35.3,52.85 36.98,54.53 41.95,54.53 43.75,56.33 43.75,56.8 44.06,57.1 44.82,57.1 48.65,60.93 48.65,62.28 P503.15
  BOTTOM w0.203: P503.15 C527.1
GPIO_3P3_6: length 57.2
  TOP w0.254: U101.E14 v6(31.64,52.38)
  L5_SIG w0.114: v6(31.64,52.38) 31.96,52.38 32.3,52.71 32.43,52.71 32.58,52.86 32.58,54.62 31.7,55.5 31.7,56.24 32.23,56.78 32.3,56.78 32.97,57.46 32.97,59.17 34.2,60.4 34.2,62.89 36.21,64.89 36.62,64.89 37.69,65.96 45.67,65.96 45.68,65.96 46.1,65.96 46.11,65.96 46.49,65.96 46.68,66.15 48.09,66.15 48.16,66.08 49.36,66.08 49.36,66.09 56.84,66.09 57.54,65.39 57.54,61.9 58.18,61.26 61.99,61.26 62.41,61.68 62.41,61.73 62.75,62.07 62.75,62.91 63.38,63.55 67.95,63.55 P503.2
  BOTTOM w0.203: P503.2 C528.1
GPIO_3P3_7: length 57.9
  TOP w0.254: U101.D12 v6(30.84,50.78)
  L8_SIG w0.114: v6(30.84,50.78) 31.29,51.23 31.77,51.23 31.97,51.44 31.97,51.59 32.42,52.04 32.58,52.04 32.85,52.31 32.85,54.94 32.75,55.04 32.75,55.47 33.05,55.77 33.06,55.77 33.39,56.1 33.4,56.1 33.7,56.4 33.7,56.41 34.33,57.03 34.33,61.09 38.19,64.94 39.89,64.94 44.71,69.77 53.98,69.77 55.13,70.91 61.99,70.91 66.43,66.47 66.68,66.47 67.83,65.32 67.83,63.67 P503.4
  BOTTOM w0.203: P503.4 66.56,60.65
GPIO_3P3_8: length 43.6
  TOP w0.254: U101.D13 v6(30.84,51.58)
  L5_SIG w0.114: v6(30.84,51.58) 31.21,51.95 33.02,51.95 34.3,53.23 34.3,57.9 36.7,60.3 37.21,60.3 38.05,61.13 48.52,61.13 49.03,60.63 63,60.63 64.02,61.64 P503.6
  BOTTOM w0.203: P503.6 64.02,60.65
GPIO_3P3_9: length 63.3
  TOP w0.254: U101.C13 v6(30.04,51.58)
  L5_SIG w0.114: v6(30.04,51.58) 30.04,52.12 28.97,53.19 28.97,57.55 27.81,58.71 27.81,60.6 27.49,60.93 27.49,66.1 27.82,66.43 28.42,66.43 29.25,67.26 29.25,70.18 30.11,71.04 35.19,71.04 38.17,68.06 40.2,68.06 40.82,67.44 47.97,67.44 48.78,68.25 59.83,68.25 62.62,65.45 62.62,64.18 61.48,63.04 P503.8
  BOTTOM w0.203: P503.8 61.48,60.65
GPIO_3P3_10: length 54.8
  TOP w0.254: U101.D14 v6(30.84,52.38)
  L5_SIG w0.114: v6(30.84,52.38) 30.42,52.38 29.34,53.46 29.34,58.76 29.68,59.1 29.68,59.81 28.2,61.29 28.2,65.29 30.28,67.37 31.65,67.37 31.82,67.2 34.78,67.2 35.32,66.65 36.67,66.65 37.22,67.2 39.28,67.2 39.7,66.79 45.48,66.79 45.68,66.98 48.8,66.98 48.93,67.11 50.29,67.11 50.89,66.51 59.15,66.51 60.21,65.45 60.21,63.67 P503.10
  BOTTOM w0.203: P503.10 C532.1
GPIO_3P3_11: length 34
  TOP w0.254: U101.F14 v6(32.44,52.38)
  L5_SIG w0.114: P503.12 55.13,63.67 47.57,63.67 47.28,63.38 40.23,63.38 39.71,62.86 37.46,62.86 37.16,63.16 36.43,63.16 35.48,62.21 35.48,60.26 33.8,58.58 33.8,53.68 32.85,52.73 32.85,52.63 32.59,52.38 v6(32.44,52.38)
GPIO_4: length 119.4
  TOP w0.254: U101.K6 v6(36.44,45.18)
  TOP w0.305: R524.1 91.29,54.11 P502.6
  L7_SIG w0.114: P502.6 90.18,52.94 90.18,50.47 94.88,45.77 113.42,45.77 113.72,46.07 117.69,46.07 118.31,45.45 130.47,45.45 133.12,42.8 v2(134.02,42.8)
  L8_SIG w0.114: P502.6 90.12,52.88 90.12,50.66 88.45,49 88.45,48.46 88.15,48.16 87.62,48.16 83.72,44.26 62.93,44.26 61.22,42.55 55.55,42.55 55.44,42.66 54.18,42.66 53.48,41.96 49.67,41.96 49.36,41.65 41.47,41.65 39.87,43.24 38.98,43.24 37.1,43.24 36.9,43.44 36.9,43.59 36.58,43.91 36.41,43.91 36.1,44.22 36.1,44.52 36.44,44.86 v6(36.44,45.18)
  BOTTOM w0.394: v2(134.02,42.8) P801.H25
GPIO_5: length 112.3
  TOP w0.254: U101.K5 v6(36.44,44.38)
  TOP w0.305: R522.1 89.04,51.29 P502.7
  L7_SIG w0.114: v2(134.02,41.53) 133.53,41.53 131.19,43.86 122.69,43.86 122.41,44.14 118.93,44.14 118.26,43.46 117.83,43.46 117.69,43.61 107.67,43.61 107.66,43.61 107.24,43.61 107.23,43.61 93.48,43.61 90.56,46.53 90.56,47.16 88.78,48.94 P502.7
  L8_SIG w0.097: 39.51,43.99 39.89,43.99
  L8_SIG w0.114: P502.7 88.78,51.23 85.35,47.8 84.46,47.8 82.25,45.58 61.42,45.58 59.88,44.05 54.3,44.05 53.6,43.35 49.92,43.35 49.67,43.1 40.78,43.1 39.89,43.99 ; 39.51,43.99 37.15,43.99 36.76,44.38 v6(36.44,44.38)
  BOTTOM w0.394: v2(134.02,41.53) P801.H26
GPIO_6: length 120.8
  TOP w0.254: U101.L5 v6(37.24,44.38)
  TOP w0.305: P502.8 88.82,54.12 R523.1
  L7_SIG w0.114: P502.8 90.62,55.93 98.94,55.93 102.88,51.99 128.92,51.99 129.29,52.36 136.55,52.36 137.03,51.88 137.03,51.84 141.11,47.76 141.11,45.87 v2(141.64,45.34)
  L8_SIG w0.114: P502.8 87.64,52.94 87.64,50.97 86.21,49.55 86.21,49.31 86.1,49.2 82.81,49.2 82.81,49.19 82.65,49.19 80.16,46.71 80.16,46.59 79.66,46.09 60.4,46.09 59.77,45.45 57.85,45.45 56.96,44.56 55.32,44.56 55.19,44.68 49.85,44.68 49.28,44.12 40.52,44.12 39.89,44.75 37.61,44.75 v6(37.24,44.38)
  BOTTOM w0.394: v2(141.64,45.34) P801.C22
GPIO_7: length 119.8
  TOP w0.254: U101.L6 v6(37.24,45.18)
  TOP w0.305: R519.1 86.65,51.14 P502.9
  L7_SIG w0.114: v2(140.37,45.34) 140.37,44.46 137.99,42.08 135.65,42.08 134.49,40.93 132.07,40.93 131.31,41.69 130.7,41.69 130.64,41.63 127.85,41.63 127.14,42.34 121.95,42.34 121.57,41.96 120.06,41.96 119.61,42.41 113.74,42.41 113.42,42.08 93.1,42.08 91.07,44.12 90.43,44.12 89.54,45 89.54,45.64 86.24,48.94 P502.9
  L8_SIG w0.114: P502.9 85.04,50.34 80.53,50.34 80.15,49.96 80.15,49.87 79.85,49.57 79.76,49.57 77.61,47.42 60.72,47.42 59.38,46.08 49.6,46.08 48.24,44.72 47.21,44.72 47.18,44.75 40.65,44.75 39.76,45.64 38.7,45.64 37.7,45.64 v6(37.24,45.18)
  BOTTOM w0.394: P801.C23 v2(140.37,45.34)
GPIO_8: length 146.8
  TOP w0.254: U101.L12 v6(37.24,50.78)
  TOP w0.305: P502.10 86.23,54.1 86.23,56.32 R520.1
  L5_SIG w0.091: v2(136.56,42.8) 137.23,42.8 137.35,42.93 137.35,43.49 137.23,43.62 136.07,43.62 135.94,43.74 135.94,44.42 135.82,44.55 134.62,44.55 134.5,44.42 134.5,43.61 134.37,43.48 133.63,43.48 133.5,43.61 133.5,44.42 133.37,44.55 132.24,44.55 132.12,44.42 132.12,42.14 132.24,42.01 134.65,42.01 134.77,42.14 134.77,43.01 135.03,43.27 135.64,43.27 135.77,43.14 135.77,42.45 135.96,42.26 138.5,42.26 138.81,42.57 138.81,50.25 136.81,52.24 131.22,52.24 129.95,53.51 124.11,53.51 123.86,53.77 103.13,53.77 102.88,54.02 99.2,54.02 97.29,55.93 85.97,55.93 85.93,55.89 85.93,55.64 86.24,55.32 P502.10
  L10_SIG w0.091: P502.10 85.04,52.88 85.04,51.06 83.34,49.37 79.99,49.37 79.95,49.33 79.32,49.33 79.28,49.37 73.44,49.37 70.11,52.7 46.16,52.7 44.46,54.4 37.96,54.4 37.05,53.49 37.05,52.34 37.63,51.75 37.63,51.17 v6(37.24,50.78)
  BOTTOM w0.203: v2(136.56,42.8) P801.G25
GPIO_9: length 117.5
  TOP w0.254: U101.K12 v6(36.44,50.78)
  L5_SIG w0.091: v2(134.02,46.61) 134.02,46.12 134.24,45.9 134.4,45.9 134.5,46 134.5,46.8 134.18,47.13 127.92,47.13 124.52,50.53 115.62,50.53 115.05,49.96 85.72,49.96 84.82,50.86 84.82,52.18 84.27,52.73 84.05,52.73 83.7,52.37 P502.11
  L10_SIG w0.091: P502.11 83.83,51.55 83.95,51.67 83.95,52.56 83.83,52.69 72.87,52.69 68.37,57.2 41.43,57.2 40.57,58.06 37.05,58.06 35.66,56.68 35.66,52.1 35.76,52.01 35.85,52.01 36.08,51.78 36.08,51.13 v6(36.44,50.78)
  BOTTOM w0.203: v2(134.02,46.61) P801.H22
GPIO_10: length 117.5
  TOP w0.254: U101.J12 v6(35.64,50.78)
  L5_SIG w0.091: P502.12 83.7,53.4 84.12,52.98 84.38,52.98 85.07,52.29 85.07,50.97 85.83,50.21 114.94,50.21 115.52,50.79 124.63,50.79 128.03,47.38 134.28,47.38 134.76,46.91 134.76,45.89 134.51,45.65 134.33,45.65 v2(134.02,45.34)
  L10_SIG w0.091: v6(35.64,50.78) 35.31,51.1 35.31,51.77 35.41,51.87 35.41,56.78 36.94,58.31 40.67,58.31 41.54,57.45 68.47,57.45 72.98,52.94 83.61,52.94 83.7,53.03 P502.12
  BOTTOM w0.203: v2(134.02,45.34) P801.H23
GPIO_11: length 117.9
  TOP w0.254: U101.H12 v6(34.84,50.78)
  L5_SIG w0.091: P502.13 81.16,52.46 81.39,52.69 81.84,52.69 82.59,53.45 82.59,54.61 83.21,55.22 84.39,55.22 84.88,54.74 84.88,53.4 85.6,52.68 102.69,52.68 103.29,52.08 128.19,52.08 130.6,49.67 134.3,49.67 135.62,48.35 135.62,46.94 v2(135.29,46.61)
  L7_SIG w0.091: v6(34.84,50.78) 34.85,50.78 34.86,50.79 35.12,50.79 35.52,50.39 39.71,50.39 39.92,50.59 39.92,50.76 40.06,50.9 44.38,50.9 45.86,52.37 70.11,52.37 73.48,55.74 78.66,55.74 79.75,54.64 79.75,53.07 80.14,52.69 81.88,52.69 82.01,52.56 82.01,51.67 81.88,51.55 P502.13
  BOTTOM w0.203: P801.G21 v2(135.29,46.61)
GPIO_12: length 117.8
  TOP w0.254: U101.H11 v6(34.84,49.98)
  L5_SIG w0.091: v2(136.56,46.61) 135.88,47.29 135.88,48.46 134.41,49.92 130.7,49.92 128.29,52.34 103.4,52.34 102.8,52.94 85.71,52.94 85.13,53.51 85.13,54.84 84.5,55.48 83.1,55.48 82.34,54.72 82.34,53.55 81.73,52.94 81.38,52.94 81.16,53.16 P502.14
  L7_SIG w0.091: v6(34.84,49.98) 34.84,50.31 34.51,50.63 34.51,50.91 34.75,51.15 44.28,51.15 45.75,52.62 70.01,52.62 73.37,55.99 78.77,55.99 80.01,54.75 80.01,53.18 80.24,52.94 81.07,52.94 81.16,53.03 P502.14
  BOTTOM w0.203: P801.G22 v2(136.56,46.61)
GPIO_13: length 121.9
  TOP w0.254: U101.J11 v6(35.64,49.98)
  L7_SIG w0.091: P502.15 78.62,52.6 78.53,52.69 77.85,52.69 77.54,52.38 77.54,51.03 76.12,49.62 75.42,49.62 73.48,47.67 52.21,47.67 51.6,48.28 49.44,48.28 49.09,47.93 42.55,47.93 42.02,47.4 39.99,47.4 39.79,47.2 39.48,47.2 39.26,47.42 38.77,47.42 38.14,48.05 37.9,48.05 37.71,48.24 37.71,48.48 37.34,48.85 37.1,48.85 36.91,49.04 36.91,49.31 36.83,49.39 36.7,49.39 36.54,49.54 36.07,49.54 v6(35.64,49.98)
  L8_SIG w0.091: P502.15 78.62,52.03 79.29,52.7 84.42,52.7 85.13,53.41 85.13,54.74 85.82,55.42 94.14,55.42 94.96,54.59 94.96,53.56 95.87,52.65 97.78,52.65 102.75,47.67 113.21,47.67 125.52,35.36 128.36,35.36 130.23,33.49 135.45,33.49 136.15,34.2 136.15,34.77 v2(136.56,35.18)
  BOTTOM w0.203: v2(136.56,35.18) P801.G31
GPIO_14: length 121.8
  TOP w0.254: U101.K11 v6(36.44,49.98)
  L7_SIG w0.091: P502.16 78.97,54.09 79.1,53.96 79.1,53.07 78.97,52.94 77.74,52.94 77.29,52.49 77.29,51.14 76.02,49.87 75.32,49.87 73.37,47.93 52.31,47.93 51.7,48.54 49.34,48.54 48.98,48.18 42.45,48.18 41.92,47.65 40.1,47.65 39.79,47.95 39.48,47.95 39.2,47.67 38.88,47.67 38.36,48.19 38.36,48.51 38.17,48.7 37.85,48.7 37.56,48.99 37.56,49.31 37.37,49.5 37.08,49.5 36.94,49.64 36.8,49.64 36.47,49.98 v6(36.44,49.98)
  L8_SIG w0.091: v2(135.29,35.18) 135.59,35.18 135.9,34.87 135.9,34.3 135.34,33.74 130.34,33.74 128.46,35.62 125.62,35.62 113.31,47.93 102.86,47.93 97.88,52.9 95.98,52.9 95.22,53.66 95.22,54.7 94.24,55.67 85.71,55.67 84.88,54.84 84.88,53.52 84.32,52.95 79.29,52.95 78.62,53.62 P502.16
  BOTTOM w0.203: v2(135.29,35.18) P801.G30
GPIO_15: length 147
  TOP w0.254: U101.L11 v6(37.24,49.98)
  L5_SIG w0.091: P502.17 76.84,51.55 78.17,52.88 79.1,52.88 79.86,53.64 79.86,54.84 81.01,55.99 85.67,55.99 85.86,56.18 97.4,56.18 99.3,54.28 102.98,54.28 103.24,54.02 123.96,54.02 124.22,53.77 130.06,53.77 131.33,52.5 136.91,52.5 139.06,50.35 139.06,42.46 138.6,42 135.86,42 135.29,42.57 v2(135.29,42.8)
  L10_SIG w0.091: v6(37.24,49.98) 36.88,49.98 36.79,50.07 36.79,53.59 37.86,54.66 44.56,54.66 46.27,52.96 70.21,52.96 73.55,49.62 79.39,49.62 79.43,49.58 79.85,49.58 79.89,49.62 83.2,49.62 83.33,49.75 83.33,50.26 83.2,50.39 80.46,50.39 80.08,50.77 79.52,50.77 79.06,50.31 78.17,50.31 77.74,50.74 77.13,50.74 76.65,50.26 75.08,50.26 74.88,50.47 74.88,51.35 75.07,51.55 P502.17
  BOTTOM w0.203: P801.G24 v2(135.29,42.8)
GPIO_16: length 112.5
  TOP w0.254: U101.M11 v6(38.04,49.98)
  L5_SIG w0.091: v2(136.56,54.23) 136.15,54.23 136.06,54.32 136.06,55.77 135.51,56.32 132.72,56.32 132.34,56.69 122.54,56.69 122.03,57.2 116.49,57.2 114.58,55.29 104.76,55.29 103.04,57.02 80.9,57.02 80.35,57.56 79.37,57.56 77.27,55.46 77.27,53.81 76.36,52.9 75.52,52.9 75.03,52.41 74.9,52.41 74.72,52.59 74.72,52.72 P502.18
  L7_SIG w0.091: v6(38.04,49.98) 38.35,49.98 38.82,49.5 40.83,49.5 41.03,49.7 47.78,49.7 48.8,50.72 70.29,50.72 72.56,52.99 74.98,52.99 P502.18
  BOTTOM w0.394: P801.G16 v2(136.56,54.23)
GPIO_17: length 112.5
  TOP w0.254: U101.M10 v6(38.04,49.18)
  L5_SIG w0.091: P502.19 74.53,51.55 75.63,52.65 76.46,52.65 77.52,53.71 77.52,55.36 79.48,57.31 80.25,57.31 80.79,56.76 102.93,56.76 104.66,55.04 114.69,55.04 116.59,56.94 121.93,56.94 122.44,56.43 132.24,56.43 132.61,56.06 135.4,56.06 135.8,55.67 135.8,54.74 v2(135.29,54.23)
  L7_SIG w0.091: v6(38.04,49.18) 38.38,49.18 38.77,48.79 38.91,48.79 39.16,49.04 39.22,49.04 39.47,48.79 39.75,48.79 39.94,48.98 39.94,49.16 40.02,49.25 40.93,49.25 41.14,49.45 47.89,49.45 48.9,50.47 70.4,50.47 72.66,52.73 74.83,52.73 74.99,52.57 74.99,51.64 74.89,51.55 P502.19
  BOTTOM w0.394: P801.G15 v2(135.29,54.23)
GPIO_18: length 125.2
  TOP w0.254: U101.J3 v6(35.64,43.58)
  TOP w0.305: P502.20 73.66,54.2 73.66,56.13 R521.1 R518.1
  L5_SIG w0.114: v2(140.37,58.04) 137.15,61.26 130.44,61.26 129.36,62.34 127.12,62.34 124.97,64.49 105.22,64.49 100.59,59.86 87.17,59.86 87.16,59.87 79.26,59.87 73.54,54.15 P502.20
  L8_SIG w0.097: 39.41,46.38 39.76,46.38
  L8_SIG w0.114: v6(35.64,43.58) 35.47,43.58 35.01,44.04 35.01,45.68 35.19,45.85 35.19,46.02 36.28,47.11 36.58,47.11 36.85,46.84 36.85,46.62 37.08,46.38 39.41,46.38 ; 39.76,46.38 39.78,46.38 40.52,45.64 47.36,45.64 48.95,47.22 50.3,47.22 50.39,47.13 51.38,47.13 51.39,47.14 54.1,47.14 54.29,47.32 59.6,47.32 60.33,48.05 67.72,48.05 73.54,53.87 P502.20
  BOTTOM w0.203: P801.D12 139.74,58.63 139.88,58.49 139.92,58.49 v2(140.37,58.04)
INPUT_VOLTAGE: length 42.1
  TOP w0.203: 121.36,15.76 DS701.A 121.36,18.14 CR701.C
  TOP w0.305: R602.2 v1(55.9,19.99)
  L7_SIG w0.114: v1(55.9,19.99) 56.41,19.48 60.21,19.48 62.37,17.32 80.18,17.32 v1(84.09,21.22)
  BOTTOM w0.254: v1(92.49,25.87) 92.24,26.12 U701.6 ; v1(92.49,25.87) 92.24,25.62 U701.7 ; v1(92.49,25.87) 92.8,25.87 v1(93.15,25.51) ; U701.36 84.03,28.62 83.53,29.12 ; v1(85.59,21.2) 86.25,21.86 U701.22 ; 85.26,30.29 85.75,29.8 U701.38
  BOTTOM w0.394: R709.1 v1(92.94,31.09)
  vias: v1(83.38,30.98) v1(83.71,29.43) v1(84.24,30.98) v1(84.57,29.43) v1(84.82,21.2) v1(98.77,26.02) v1(98.77,25.13) v1(98.77,24.27) v7(117.74,18.72) v7(117.74,17) v7(119.26,18.72) v7(119.26,17) v7(123.71,18.72) v7(123.71,17) v7(125.23,18.72) v7(125.23,17)
JTAG_TDI: length 1.6
  TOP w0.305: R815.2 140.04,34.85 v2(140.37,35.18)
  BOTTOM w0.394: v2(140.37,35.18) P801.D30
JTAG_TDO: length 1.6
  TOP w0.305: v2(140.37,33.91) 140.07,34.21 R815.1
  BOTTOM w0.394: v2(140.37,33.91) P801.D31
LDO_VCO_2P5: length 3.4
  BOTTOM w0.254: U401.15 86.54,68.07 86.54,67.75 86.55,67.74 86.55,67.23 86.26,66.94 C412.1 86.26,66.01 86.31,65.96 C413.1
LF_EXT_CAP: length 3.1
  BOTTOM w0.203: 90.4,66.59 C410.2
  BOTTOM w0.254: U401.7 90.54,67.88 90.54,66.69 C410.2 ; R415.2 89.95,66.58 89.96,66.59 90.4,66.59
LF_PLL2: length 2.2
  BOTTOM w0.254: U401.14 87.04,67.52 87.25,67.31 C412.2
ORX1+: length 8.1
  BOTTOM w0.127: 23.36,53.8 23.4,53.61 C232.2
  BOTTOM w0.203: v5(28.84,50.38) arc(28.64,50.41) 28.43,50.42 arc(25.7,51.21) 23.68,53.21 arc(23.61,53.31) 23.55,53.42 arc(23.45,53.61) 23.36,53.8 arc(23.12,54.11) 22.82,54.35 arc(22.73,54.4) L231.1
ORX1-: length 8.5
  BOTTOM w0.127: C232.1 23.75,53.82 23.66,53.98 ; C232.1 23.77,53.84 ; C232.1 23.85,53.87
  BOTTOM w0.203: 23.75,53.82 23.85,53.87 ; 23.75,53.82 23.86,53.59 arc(23.92,53.49) 23.98,53.4 arc(25.88,51.52) 28.44,50.78 arc(28.53,50.78) 28.61,50.8 arc(28.71,50.85) 28.8,50.91 arc(28.86,51.04) v5(28.84,51.18) ; 23.75,53.82 arc(23.71,53.9) 23.66,53.98 ; 23.66,53.98 23.74,53.85 23.77,53.84 ; 23.66,53.98 arc(23.54,54.24) 23.47,54.52 arc(23.45,54.71) L230.1
ORX2+: length 7.7
  BOTTOM w0.203: C240.2 24.1,39.26 ; 24.1,39.26 arc(24.03,39.15) 23.95,39.03 arc(23.81,38.71) 23.74,38.36 L239.1 ; 24.1,39.26 arc(25.78,41.18) 27.87,42.64 arc(28.14,42.74) 28.43,42.78 arc(28.52,42.77) 28.61,42.75 arc(28.71,42.71) 28.8,42.64 arc(28.86,42.51) v5(28.84,42.38)
ORX2-: length 7.7
  BOTTOM w0.203: 22.96,38.73 23.22,38.84 arc(23.46,39) 23.65,39.23 23.74,39.36 arc(23.78,39.42) 23.83,39.49 ; C240.1 23.83,39.49 ; 23.83,39.49 arc(25.56,41.46) 27.71,42.95 arc(28.06,43.09) 28.43,43.13 arc(28.64,43.14) v5(28.84,43.18)
OUT: length 4.9
  BOTTOM w0.203: Y401.4 Y403.3 Y402.4 111.2,71.42 110.48,72.15 R410.1
RESETB: length 117.3
  TOP w0.254: U101.J4 v6(35.64,44.38)
  TOP w0.394: TP804.1 128.26,61.2 R802.1
  L5_SIG w0.114: TP804.1 127.59,61.01 118.63,61.01 117.35,59.73 117.1,59.73 113.55,56.18 106.31,56.18 103.8,58.69 79.1,58.69 74.81,54.4 74.81,53.64 74.09,52.92 v5(40.9,52.92) 40.83,52.92 39.89,51.98 38.65,51.98 38.44,51.78 38.44,48.22 39.23,47.44 39.23,46.62 39.22,46.61 39.22,45.04 39,44.81 38.74,44.81 38.44,44.51 38.44,44.23 38.14,43.93 36.08,43.93 v6(35.64,44.38)
  BOTTOM w0.305: R502.2 40.16,51.31 40.9,52.05 v5(40.9,52.92)
RX1+: length 8.5
  TOP w0.203: C207.2 23.2,51.94 ; 23.2,51.94 arc(24.27,51.7) 25.16,51.04 27.12,48.81 arc(27.72,48.38) 28.44,48.22 arc(28.58,48.19) 28.7,48.11 U101.A9 ; 23.2,51.94 arc(23.11,51.94) 23.02,51.94 arc(22.54,51.87) L205.1
RX1-: length 8.4
  TOP w0.203: U101.A10 28.74,48.68 arc(28.63,48.6) 28.5,48.58 28.44,48.58 arc(27.86,48.7) 27.39,49.05 25.42,51.28 arc(24.42,52.02) 23.21,52.3 ; C207.1 23.21,52.3 ; 23.21,52.3 arc(23.11,52.3) 23.01,52.3 arc(22.53,52.36) L206.1
RX1_ENABLE: length 64.2
  TOP w0.254: U101.M5 v6(38.04,44.38)
  TOP w0.305: R508.1 76.27,65.01 P501.7
  L5_SIG w0.114: P501.7 75.51,64.94 74.3,66.15 73.3,66.15 71.89,64.74 71.89,60.12 69.34,57.56 40.89,57.56 38.36,55.04 37.35,55.04 36.08,53.77 36.08,52.96 35.3,52.19 35.3,47.43 35.49,47.24 35.69,47.24 36.06,46.87 36.06,46.03 36.77,45.32 36.77,45.16 37.2,44.74 37.67,44.74 v6(38.04,44.38)
  BOTTOM w0.203: 76.21,66.42 P501.7
RX2+: length 7.7
  TOP w0.203: 23.21,42.44 23.2,42.43 C216.1 ; 23.21,42.44 arc(23.12,42.45) 23.02,42.45 arc(22.54,42.38) L214.1 ; 23.21,42.44 arc(23.98,42.55) 24.7,42.86 arc(25.8,43.55) 26.84,44.31 arc(27.61,44.76) 28.47,44.98 arc(28.69,44.93) U101.A5
RX2-: length 7.7
  TOP w0.203: U101.A6 28.7,45.44 arc(28.58,45.36) 28.44,45.33 arc(27.47,45.09) 26.62,44.59 arc(25.59,43.84) 24.52,43.17 arc(23.88,42.89) 23.19,42.8 ; 23.19,42.8 23.2,42.81 C216.2 ; 23.19,42.8 arc(23.11,42.8) 23.02,42.8 arc(22.54,42.87) L215.1
RX2_ENABLE: length 53.4
  TOP w0.254: U101.M7 v6(38.04,46.78)
  TOP w0.305: R509.1 76.27,62.34 P501.8
  L5_SIG w0.114: v6(38.04,46.78) 38.37,47.11 38.37,47.72 38.05,48.04 37.9,48.04 37.63,48.31 37.63,48.54 37.63,48.54 37.63,51.88 38.49,52.74 40.09,52.74 41.68,54.33 68.71,54.33 76.21,61.83 P501.8
  BOTTOM w0.203: 76.21,60.93 P501.8
RX_EXTLO+: length 6.7
  TOP w0.203: U101.B8 v6(29.24,47.58)
  L10_SIG w0.091: v6(29.24,47.58) 29.24,46.9 arc(29.19,46.77) 29.06,46.72 28.68,46.72 arc(28.62,46.73) 28.57,46.76 arc(28.42,46.87) 28.23,46.9 24.96,46.9 arc(24.74,46.95) v5(24.56,47.07)
  BOTTOM w0.203: C332.2 v5(24.56,47.07)
RX_EXTLO-: length 6.6
  TOP w0.203: U101.B7 v6(29.24,45.98)
  L10_SIG w0.091: v6(29.24,45.98) 29.24,46.29 arc(29.19,46.41) 29.06,46.47 28.68,46.47 arc(28.52,46.5) 28.39,46.58 arc(28.32,46.63) 28.23,46.65 24.99,46.65 arc(24.68,46.52) 24.56,46.22 v5(24.56,46.15)
  BOTTOM w0.203: C333.2 v5(24.56,46.15)
SERDIN0+: length 3
  BOTTOM w0.203: C508.1 146.02,40.57 arc(145.87,40.47) 145.7,40.44 143.75,40.44 arc(143.61,40.5) 143.55,40.64 P801.A26
SERDIN0-: length 3
  BOTTOM w0.203: P801.A27 143.55,39.88 arc(143.61,40.02) 143.75,40.08 145.7,40.08 arc(145.87,40.05) 146.02,39.95 C507.1
SERDIN1+: length 1.4
  TOP w0.203: v2(141.64,70.74) C510.1
  BOTTOM w0.203: P801.C2 v2(141.64,70.74)
SERDIN1-: length 2.2
  TOP w0.203: v2(141.64,69.47) C509.1 v2(141.64,69.47)
  BOTTOM w0.203: 141.19,69.92 141.19,69.94 141.03,70.1 P801.C3 141.19,69.92 ; 141.19,69.92 v2(141.64,69.47)
SERDIN2+: length 3
  BOTTOM w0.203: P801.A30 143.55,35.56 arc(143.61,35.42) 143.75,35.36 145.7,35.36 arc(145.87,35.39) 146.02,35.49 C512.1
SERDIN2-: length 3
  BOTTOM w0.203: C511.1 146.02,34.87 arc(145.87,34.97) 145.7,35 143.75,35 arc(143.61,34.94) 143.55,34.8 P801.A31
SERDIN3+: length 3
  BOTTOM w0.203: P801.A22 143.55,45.72 arc(143.61,45.58) 143.75,45.52 145.7,45.52 arc(145.87,45.55) 146.02,45.65 C514.1
SERDIN3-: length 3
  BOTTOM w0.203: C513.1 146.02,45.03 arc(145.87,45.13) 145.7,45.16 143.75,45.16 arc(143.61,45.1) 143.55,44.96 P801.A23
SERDOUT0+: length 3
  BOTTOM w0.203: P801.A2 143.55,71.12 arc(143.61,70.98) 143.75,70.92 145.7,70.92 arc(145.87,70.95) 146.02,71.05 C516.1
SERDOUT0-: length 3
  BOTTOM w0.203: C515.1 146.02,70.43 arc(145.87,70.53) 145.7,70.56 143.75,70.56 arc(143.61,70.5) 143.55,70.36 P801.A3
SERDOUT1+: length 3
  BOTTOM w0.203: P801.A6 143.55,66.04 arc(143.61,65.9) 143.75,65.84 145.7,65.84 arc(145.87,65.87) 146.02,65.97 C518.1
SERDOUT1-: length 3
  BOTTOM w0.203: P801.A7 143.55,65.28 arc(143.61,65.42) 143.75,65.48 145.7,65.48 arc(145.87,65.45) 146.02,65.35 C517.1
SERDOUT2+: length 1.4
  TOP w0.203: C520.1 141.67,65.63 v2(141.67,65.65)
  BOTTOM w0.203: v2(141.67,65.65) 141.66,65.65 P801.C6
SERDOUT2-: length 1.4
  TOP w0.203: v2(141.64,64.39) C519.1
  BOTTOM w0.203: v2(141.64,64.39) P801.C7
SERDOUT3+: length 3
  BOTTOM w0.203: P801.A10 143.55,60.96 arc(143.61,60.82) 143.75,60.76 145.7,60.76 arc(145.87,60.79) 146.02,60.89 C522.1
SERDOUT3-: length 3
  BOTTOM w0.203: P801.A11 143.55,60.2 arc(143.61,60.34) 143.75,60.4 145.7,60.4 arc(145.87,60.37) 146.02,60.27 C521.1
SNRXA+: length 15.7
  TOP w0.254: U101.E4 v6(31.64,43.58)
  L10_SIG w0.091: v6(31.64,43.58) 31.82,43.4 arc(31.96,43.18) 32.01,42.92 32.01,41.99 arc(31.9,41.72) 31.62,41.6 arc(31.54,41.6) 31.47,41.58 arc(31.44,41.57) 31.42,41.56 arc(31.32,41.51) 31.24,41.44 arc(31.02,41.3) 30.76,41.24 30.6,41.24 arc(30.31,41.12) 30.18,40.83 30.18,36.44 arc(30.13,35.94) 29.93,35.47 29.69,35.06 arc(29.45,34.4) 29.47,33.69 arc(29.54,33.05) 29.47,32.41 arc(29.45,32.35) 29.43,32.3 arc(29.42,32.15) v5(29.49,32.01)
  BOTTOM w0.203: 29.08,31.41 28.96,31.15 arc(28.85,30.73) L222.1 ; 29.08,31.41 29.19,31.65 arc(29.32,31.85) v5(29.49,32.01) ; 29.08,31.41 C224.1
SNRXA-: length 15.7
  TOP w0.254: U101.D4 v6(30.84,43.58)
  L10_SIG w0.091: v6(30.84,43.58) 31.12,43.58 arc(31.24,43.53) 31.28,43.42 arc(31.29,43.36) 31.33,43.31 31.38,43.26 arc(31.42,43.16) 31.38,43.07 31.28,42.97 arc(31.22,42.88) 31.2,42.78 arc(31.21,42.74) 31.23,42.71 31.42,42.51 arc(31.46,42.46) 31.47,42.4 arc(31.46,42.31) 31.41,42.24 31.25,42.08 arc(31.21,42.03) 31.2,41.96 arc(31.16,41.78) 31.06,41.62 arc(30.92,41.53) 30.76,41.5 30.6,41.5 arc(30.13,41.3) 29.93,40.83 29.93,36.43 arc(29.88,36) 29.71,35.6 29.47,35.19 arc(29.2,34.44) 29.22,33.64 arc(29.28,33.05) 29.22,32.46 arc(29.15,32.32) v5(29.01,32.24)
  BOTTOM w0.203: 28.76,31.56 28.87,31.8 arc(28.95,32.01) v5(29.01,32.24) ; 28.76,31.56 C224.2 ; 28.76,31.56 28.64,31.3 arc(28.39,30.94) L223.1
